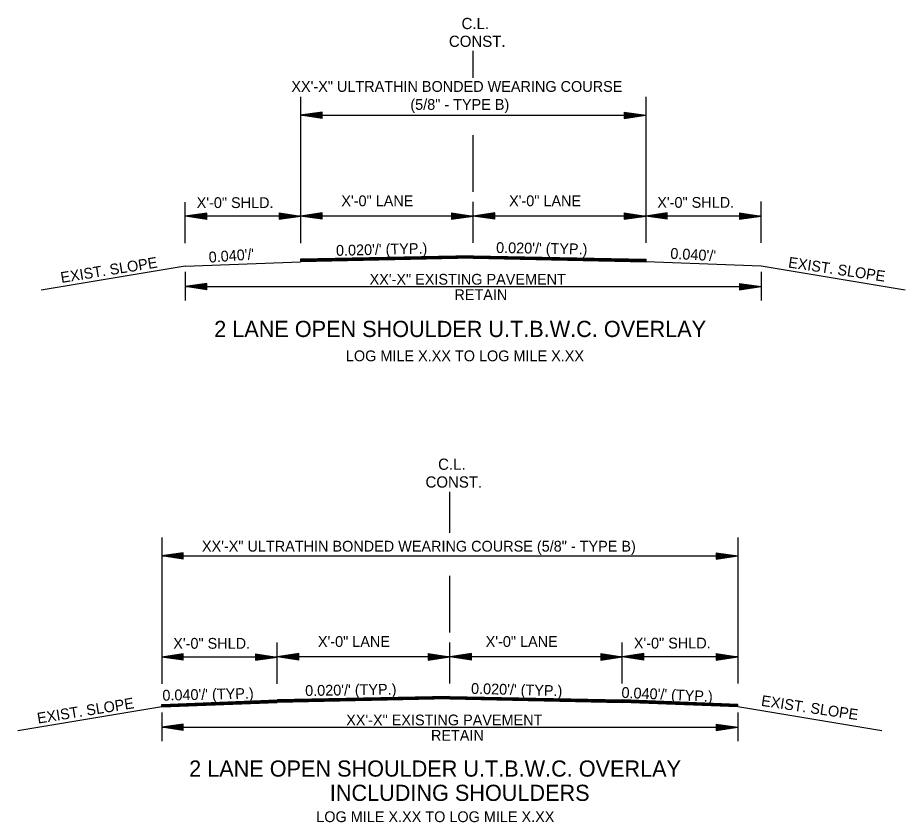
# Model space of a CAD drawing. Extents: x 544199 to 1930787, y -1968972 to 596640.
# Drawn here: x 551654 to 552271, y -1951988 to -1951428 of the extents above; entities that cross this region are included whole.
import ezdxf

# ---------------------------------------------------------------- set-up
doc = ezdxf.new("R2010")
doc.units = 0
doc.layers.add('Default', color=7, linetype='Continuous')
doc.layers.add('R_Draft', color=7, linetype='Continuous')

msp = doc.modelspace()

# ---------------------------------------------------------------- linework, layer by layer
at = {"layer": 'R_Draft'}
for p, q in [((551970.96, -1951470.01), (551970.96, -1951451.34)), ((551850.96, -1951483.29), (551850.96, -1951585.02)), ((551865.96, -1951493.8), (551850.96, -1951496.05)), ((551850.96, -1951496.05), (552090.89, -1951496.05)), ((551865.96, -1951498.3), (551850.96, -1951496.05)), ((551865.96, -1951494.18), (551853.46, -1951496.05)), ((551865.96, -1951497.93), (551853.46, -1951496.05)), ((551865.96, -1951494.56), (551856.04, -1951496.05)), ((551865.96, -1951497.54), (551856.04, -1951496.05)), ((551865.96, -1951494.93), (551858.54, -1951496.05)), ((551865.96, -1951497.17), (551858.54, -1951496.05)), ((551865.96, -1951495.32), (551861.08, -1951496.05)), ((551865.96, -1951496.78), (551861.08, -1951496.05)), ((551865.96, -1951495.7), (551863.59, -1951496.05)), ((551865.96, -1951496.4), (551863.59, -1951496.05)), ((551865.96, -1951498.3), (551865.96, -1951493.8)), ((552075.89, -1951493.8), (552090.89, -1951496.05)), ((552075.89, -1951493.8), (552075.89, -1951498.3)), ((552075.89, -1951494.18), (552088.38, -1951496.05)), ((552075.89, -1951494.56), (552085.8, -1951496.05)), ((552075.89, -1951494.93), (552083.3, -1951496.05)), ((552075.89, -1951495.32), (552080.76, -1951496.05)), ((552075.89, -1951495.7), (552078.26, -1951496.05)), ((552075.89, -1951498.3), (552090.89, -1951496.05)), ((552075.89, -1951496.79), (552080.76, -1951496.05)), ((552075.89, -1951497.54), (552085.8, -1951496.05)), ((552075.89, -1951497.93), (552088.38, -1951496.05)), ((552075.89, -1951497.17), (552083.3, -1951496.05)), ((552075.89, -1951496.4), (552078.26, -1951496.05)), ((551970.96, -1951549.29), (551970.96, -1951509.94)), ((551770.7, -1951585.02), (551770.7, -1951556.47)), ((551970.96, -1951584.85), (551970.96, -1951556.3)), ((552171.15, -1951584.85), (552171.15, -1951556.13)), ((551785.7, -1951564.11), (551770.7, -1951566.36)), ((551850.96, -1951566.36), (551770.7, -1951566.36)), ((551785.7, -1951568.61), (551770.7, -1951566.36)), ((551785.7, -1951564.49), (551773.2, -1951566.36)), ((551785.7, -1951568.24), (551773.2, -1951566.36)), ((551785.7, -1951564.87), (551775.78, -1951566.36)), ((551785.7, -1951567.86), (551775.78, -1951566.36)), ((551785.7, -1951565.25), (551778.28, -1951566.36)), ((551785.7, -1951567.48), (551778.28, -1951566.36)), ((551785.7, -1951565.63), (551780.82, -1951566.36)), ((551785.7, -1951567.09), (551780.82, -1951566.36)), ((551785.7, -1951566.01), (551783.33, -1951566.36)), ((551785.7, -1951566.72), (551783.33, -1951566.36)), ((551785.7, -1951568.61), (551785.7, -1951564.11)), ((551835.96, -1951563.94), (551850.96, -1951566.19)), ((551835.96, -1951563.94), (551835.96, -1951568.44)), ((551835.96, -1951564.32), (551848.45, -1951566.19)), ((551835.96, -1951564.7), (551845.87, -1951566.19)), ((551835.96, -1951565.08), (551843.38, -1951566.19)), ((551835.96, -1951565.47), (551840.83, -1951566.19)), ((551835.96, -1951565.84), (551838.33, -1951566.19)), ((551835.96, -1951568.44), (551850.96, -1951566.19)), ((551835.96, -1951566.93), (551840.83, -1951566.19)), ((551835.96, -1951567.69), (551845.87, -1951566.19)), ((551835.96, -1951568.07), (551848.45, -1951566.19)), ((551835.96, -1951567.31), (551843.38, -1951566.19)), ((551835.96, -1951566.55), (551838.33, -1951566.19)), ((551865.96, -1951563.94), (551850.96, -1951566.19)), ((551970.96, -1951566.19), (551850.96, -1951566.19)), ((551865.96, -1951568.44), (551850.96, -1951566.19)), ((551865.96, -1951564.32), (551853.46, -1951566.19)), ((551865.96, -1951568.07), (551853.46, -1951566.19)), ((551865.96, -1951564.7), (551856.04, -1951566.19)), ((551865.96, -1951567.69), (551856.04, -1951566.19)), ((551865.96, -1951565.08), (551858.54, -1951566.19)), ((551865.96, -1951567.31), (551858.54, -1951566.19)), ((551865.96, -1951565.46), (551861.08, -1951566.19)), ((551865.96, -1951566.92), (551861.08, -1951566.19)), ((551865.96, -1951565.84), (551863.59, -1951566.19)), ((551865.96, -1951566.55), (551863.59, -1951566.19)), ((551865.96, -1951568.44), (551865.96, -1951563.94)), ((551955.96, -1951563.94), (551970.96, -1951566.19)), ((551955.96, -1951563.94), (551955.96, -1951568.44)), ((551955.96, -1951564.32), (551968.45, -1951566.19)), ((551955.96, -1951564.7), (551965.87, -1951566.19)), ((551955.96, -1951565.08), (551963.38, -1951566.19)), ((551955.96, -1951565.47), (551960.83, -1951566.19)), ((551955.96, -1951565.84), (551958.33, -1951566.19)), ((551955.96, -1951568.44), (551970.96, -1951566.19)), ((551955.96, -1951566.93), (551960.83, -1951566.19)), ((551955.96, -1951567.69), (551965.87, -1951566.19)), ((551955.96, -1951568.07), (551968.45, -1951566.19)), ((551955.96, -1951567.31), (551963.38, -1951566.19)), ((551955.96, -1951566.55), (551958.33, -1951566.19)), ((551985.96, -1951563.94), (551970.96, -1951566.19)), ((552090.89, -1951566.19), (551970.96, -1951566.19)), ((551985.96, -1951568.44), (551970.96, -1951566.19)), ((551985.96, -1951564.32), (551973.46, -1951566.19)), ((551985.96, -1951568.07), (551973.46, -1951566.19)), ((551985.96, -1951564.7), (551976.04, -1951566.19)), ((551985.96, -1951567.69), (551976.04, -1951566.19)), ((551985.96, -1951565.08), (551978.54, -1951566.19)), ((551985.96, -1951567.31), (551978.54, -1951566.19)), ((551985.96, -1951565.46), (551981.08, -1951566.19)), ((551985.96, -1951566.92), (551981.08, -1951566.19)), ((551985.96, -1951565.84), (551983.59, -1951566.19)), ((551985.96, -1951566.55), (551983.59, -1951566.19)), ((551985.96, -1951568.44), (551985.96, -1951563.94)), ((552075.89, -1951563.94), (552090.89, -1951566.19)), ((552075.89, -1951563.94), (552075.89, -1951568.44)), ((552075.89, -1951564.32), (552088.38, -1951566.19)), ((552075.89, -1951564.7), (552085.8, -1951566.19)), ((552075.89, -1951565.08), (552083.3, -1951566.19)), ((552075.89, -1951565.47), (552080.76, -1951566.19)), ((552075.89, -1951565.84), (552078.26, -1951566.19)), ((552075.89, -1951568.44), (552090.89, -1951566.19)), ((552075.89, -1951566.93), (552080.76, -1951566.19)), ((552075.89, -1951567.69), (552085.8, -1951566.19)), ((552075.89, -1951568.07), (552088.38, -1951566.19)), ((552075.89, -1951567.31), (552083.3, -1951566.19)), ((552075.89, -1951566.55), (552078.26, -1951566.19)), ((552105.89, -1951563.94), (552090.89, -1951566.19)), ((552171.15, -1951566.19), (552090.89, -1951566.19)), ((552105.89, -1951568.44), (552090.89, -1951566.19)), ((552105.89, -1951564.32), (552093.39, -1951566.19)), ((552105.89, -1951568.07), (552093.39, -1951566.19)), ((552105.89, -1951564.7), (552095.97, -1951566.19)), ((552105.89, -1951567.69), (552095.97, -1951566.19)), ((552105.89, -1951565.08), (552098.47, -1951566.19)), ((552105.89, -1951567.31), (552098.47, -1951566.19)), ((552105.89, -1951565.46), (552101.01, -1951566.19)), ((552105.89, -1951566.92), (552101.01, -1951566.19)), ((552105.89, -1951565.84), (552103.52, -1951566.19)), ((552105.89, -1951566.55), (552103.52, -1951566.19)), ((552105.89, -1951568.44), (552105.89, -1951563.94)), ((552156.15, -1951563.94), (552171.15, -1951566.19)), ((552156.15, -1951563.94), (552156.15, -1951568.44)), ((552156.15, -1951564.32), (552168.64, -1951566.19)), ((552156.15, -1951564.7), (552166.06, -1951566.19)), ((552156.15, -1951565.08), (552163.56, -1951566.19)), ((552156.15, -1951565.47), (552161.02, -1951566.19)), ((552156.15, -1951565.84), (552158.52, -1951566.19)), ((552156.15, -1951568.44), (552171.15, -1951566.19)), ((552156.15, -1951566.93), (552161.02, -1951566.19)), ((552156.15, -1951567.69), (552166.06, -1951566.19)), ((552156.15, -1951568.07), (552168.64, -1951566.19)), ((552156.15, -1951567.31), (552163.56, -1951566.19)), ((552156.15, -1951566.55), (552158.52, -1951566.19)), ((551970.96, -1951593.8), (551850.96, -1951596.2)), ((551850.96, -1951596.2), (551850.99, -1951597.9)), ((551970.97, -1951594.1), (551850.97, -1951596.5)), ((551970.97, -1951594.4), (551850.97, -1951596.8)), ((551970.98, -1951594.7), (551850.98, -1951597.1)), ((551970.98, -1951595), (551850.98, -1951597.4)), ((551970.99, -1951595.3), (551850.99, -1951597.7)), ((551970.99, -1951595.5), (551850.99, -1951597.9)), ((551970.93, -1951595.3), (552090.93, -1951597.7)), ((551970.93, -1951595.5), (552090.93, -1951597.9)), ((551970.94, -1951594.7), (552090.94, -1951597.1)), ((551970.94, -1951595), (552090.94, -1951597.4)), ((551970.95, -1951594.1), (552090.95, -1951596.5)), ((551970.95, -1951594.4), (552090.95, -1951596.8)), ((551970.96, -1951593.8), (552090.96, -1951596.2)), ((552090.96, -1951596.2), (552090.93, -1951597.9)), ((551770.7, -1951601.11), (551670.63, -1951617.79)), ((551770.7, -1951601.11), (551850.99, -1951597.9)), ((552171.22, -1951601.11), (552090.93, -1951597.9)), ((552271.29, -1951617.79), (552171.22, -1951601.11)), ((551770.7, -1951604.97), (551770.7, -1951624.97)), ((552171.15, -1951604.97), (552171.15, -1951624.97)), ((551785.7, -1951612.97), (551770.7, -1951615.22)), ((551770.7, -1951615.22), (552171.15, -1951615.22)), ((551785.7, -1951617.47), (551770.7, -1951615.22)), ((551785.7, -1951613.34), (551773.2, -1951615.22)), ((551785.7, -1951617.09), (551773.2, -1951615.22)), ((551785.7, -1951613.72), (551775.78, -1951615.22)), ((551785.7, -1951616.71), (551775.78, -1951615.22)), ((551785.7, -1951614.1), (551778.28, -1951615.22)), ((551785.7, -1951616.33), (551778.28, -1951615.22)), ((551785.7, -1951614.48), (551780.82, -1951615.22)), ((551785.7, -1951615.94), (551780.82, -1951615.22)), ((551785.7, -1951614.86), (551783.33, -1951615.22)), ((551785.7, -1951615.57), (551783.33, -1951615.22)), ((551785.7, -1951617.47), (551785.7, -1951612.97)), ((552156.15, -1951612.97), (552171.15, -1951615.22)), ((552156.15, -1951612.97), (552156.15, -1951617.47)), ((552156.15, -1951613.34), (552168.64, -1951615.22)), ((552156.15, -1951613.72), (552166.06, -1951615.22)), ((552156.15, -1951614.1), (552163.56, -1951615.22)), ((552156.15, -1951614.49), (552161.02, -1951615.22)), ((552156.15, -1951614.86), (552158.52, -1951615.22)), ((552156.15, -1951617.47), (552171.15, -1951615.22)), ((552156.15, -1951615.95), (552161.02, -1951615.22)), ((552156.15, -1951616.71), (552166.06, -1951615.22)), ((552156.15, -1951617.09), (552168.64, -1951615.22)), ((552156.15, -1951616.33), (552163.56, -1951615.22)), ((552156.15, -1951615.57), (552158.52, -1951615.22)), ((551954.68, -1951786.52), (551954.68, -1951757.88)), ((551754.42, -1951789.83), (551754.42, -1951891.56)), ((551769.42, -1951800.34), (551754.42, -1951802.59)), ((551769.42, -1951800.72), (551756.93, -1951802.59)), ((551769.42, -1951801.1), (551759.51, -1951802.59)), ((551769.42, -1951804.84), (551769.42, -1951800.34)), ((552139.87, -1951800.34), (552154.87, -1951802.59)), ((552139.87, -1951800.34), (552139.87, -1951804.84)), ((552139.87, -1951800.72), (552152.36, -1951802.59)), ((552139.87, -1951801.1), (552149.78, -1951802.59)), ((551754.42, -1951802.59), (552154.87, -1951802.59)), ((551769.42, -1951804.84), (551754.42, -1951802.59)), ((551769.42, -1951804.47), (551756.93, -1951802.59)), ((551769.42, -1951804.08), (551759.51, -1951802.59)), ((551769.42, -1951801.47), (551762, -1951802.59)), ((551769.42, -1951803.71), (551762, -1951802.59)), ((551769.42, -1951801.86), (551764.55, -1951802.59)), ((551769.42, -1951803.32), (551764.55, -1951802.59)), ((551769.42, -1951802.24), (551767.05, -1951802.59)), ((551769.42, -1951802.94), (551767.05, -1951802.59)), ((552139.87, -1951801.47), (552147.29, -1951802.59)), ((552139.87, -1951801.86), (552144.74, -1951802.59)), ((552139.87, -1951802.24), (552142.24, -1951802.59)), ((552139.87, -1951804.84), (552154.87, -1951802.59)), ((552139.87, -1951803.33), (552144.74, -1951802.59)), ((552139.87, -1951804.08), (552149.78, -1951802.59)), ((552139.87, -1951804.47), (552152.36, -1951802.59)), ((552139.87, -1951803.71), (552147.29, -1951802.59)), ((552139.87, -1951802.94), (552142.24, -1951802.59)), ((551954.68, -1951855.83), (551954.68, -1951816.48)), ((551834.68, -1951891.39), (551834.68, -1951862.84)), ((551834.68, -1951891.56), (551834.68, -1951862.84)), ((551954.68, -1951891.39), (551954.68, -1951862.84)), ((552074.61, -1951872.73), (552074.61, -1951862.84)), ((552074.61, -1951891.39), (552074.61, -1951862.84)), ((551769.42, -1951870.65), (551754.42, -1951872.9)), ((551834.68, -1951872.9), (551754.42, -1951872.9)), ((551769.42, -1951875.15), (551754.42, -1951872.9)), ((551769.42, -1951871.03), (551756.93, -1951872.9)), ((551769.42, -1951874.78), (551756.93, -1951872.9)), ((551769.42, -1951871.41), (551759.51, -1951872.9)), ((551769.42, -1951874.4), (551759.51, -1951872.9)), ((551769.42, -1951871.79), (551762, -1951872.9)), ((551769.42, -1951874.02), (551762, -1951872.9)), ((551769.42, -1951872.17), (551764.55, -1951872.9)), ((551769.42, -1951873.63), (551764.55, -1951872.9)), ((551769.42, -1951872.55), (551767.05, -1951872.9)), ((551769.42, -1951873.26), (551767.05, -1951872.9)), ((551769.42, -1951875.15), (551769.42, -1951870.65)), ((551819.68, -1951870.65), (551834.68, -1951872.9)), ((551819.68, -1951870.65), (551819.68, -1951875.15)), ((551819.68, -1951871.03), (551832.18, -1951872.9)), ((551819.68, -1951871.41), (551829.6, -1951872.9)), ((551819.68, -1951871.79), (551827.1, -1951872.9)), ((551819.68, -1951872.18), (551824.56, -1951872.9)), ((551819.68, -1951872.55), (551822.05, -1951872.9)), ((551819.68, -1951875.15), (551834.68, -1951872.9)), ((551819.68, -1951873.64), (551824.56, -1951872.9)), ((551819.68, -1951874.4), (551829.6, -1951872.9)), ((551819.68, -1951874.78), (551832.18, -1951872.9)), ((551819.68, -1951874.02), (551827.1, -1951872.9)), ((551819.68, -1951873.26), (551822.05, -1951872.9)), ((551849.68, -1951870.48), (551834.68, -1951872.73)), ((551954.68, -1951872.73), (551834.68, -1951872.73)), ((551849.68, -1951874.98), (551834.68, -1951872.73)), ((551849.68, -1951870.86), (551837.19, -1951872.73)), ((551849.68, -1951874.61), (551837.19, -1951872.73)), ((551849.68, -1951871.24), (551839.77, -1951872.73)), ((551849.68, -1951874.23), (551839.77, -1951872.73)), ((551849.68, -1951871.62), (551842.26, -1951872.73)), ((551849.68, -1951873.85), (551842.26, -1951872.73)), ((551849.68, -1951872), (551844.81, -1951872.73)), ((551849.68, -1951873.46), (551844.81, -1951872.73)), ((551849.68, -1951872.38), (551847.31, -1951872.73)), ((551849.68, -1951873.09), (551847.31, -1951872.73)), ((551849.68, -1951874.98), (551849.68, -1951870.48)), ((551939.68, -1951870.48), (551954.68, -1951872.73)), ((551939.68, -1951870.48), (551939.68, -1951874.98)), ((551939.68, -1951870.86), (551952.18, -1951872.73)), ((551939.68, -1951871.24), (551949.6, -1951872.73)), ((551939.68, -1951871.62), (551947.1, -1951872.73)), ((551939.68, -1951872.01), (551944.56, -1951872.73)), ((551939.68, -1951872.38), (551942.05, -1951872.73)), ((551939.68, -1951874.98), (551954.68, -1951872.73)), ((551939.68, -1951873.47), (551944.56, -1951872.73)), ((551939.68, -1951874.23), (551949.6, -1951872.73)), ((551939.68, -1951874.61), (551952.18, -1951872.73)), ((551939.68, -1951873.85), (551947.1, -1951872.73)), ((551939.68, -1951873.09), (551942.05, -1951872.73)), ((551969.68, -1951870.48), (551954.68, -1951872.73)), ((552074.61, -1951872.73), (551954.68, -1951872.73)), ((551969.68, -1951874.98), (551954.68, -1951872.73)), ((551969.68, -1951870.86), (551957.19, -1951872.73)), ((551969.68, -1951874.61), (551957.19, -1951872.73)), ((551969.68, -1951871.24), (551959.77, -1951872.73)), ((551969.68, -1951874.23), (551959.77, -1951872.73)), ((551969.68, -1951871.62), (551962.26, -1951872.73)), ((551969.68, -1951873.85), (551962.26, -1951872.73)), ((551969.68, -1951872), (551964.81, -1951872.73)), ((551969.68, -1951873.46), (551964.81, -1951872.73)), ((551969.68, -1951872.38), (551967.31, -1951872.73)), ((551969.68, -1951873.09), (551967.31, -1951872.73)), ((551969.68, -1951874.98), (551969.68, -1951870.48)), ((552059.61, -1951870.48), (552074.61, -1951872.73)), ((552059.61, -1951870.48), (552059.61, -1951874.98)), ((552059.61, -1951870.86), (552072.1, -1951872.73)), ((552059.61, -1951871.24), (552069.52, -1951872.73)), ((552059.61, -1951871.62), (552067.03, -1951872.73)), ((552059.61, -1951872.01), (552064.48, -1951872.73)), ((552059.61, -1951872.38), (552061.98, -1951872.73)), ((552059.61, -1951874.98), (552074.61, -1951872.73)), ((552059.61, -1951873.47), (552064.48, -1951872.73)), ((552059.61, -1951874.23), (552069.52, -1951872.73)), ((552059.61, -1951874.61), (552072.1, -1951872.73)), ((552059.61, -1951873.85), (552067.03, -1951872.73)), ((552059.61, -1951873.09), (552061.98, -1951872.73)), ((552089.61, -1951870.48), (552074.61, -1951872.73)), ((552074.61, -1951891.39), (552074.61, -1951872.73)), ((552154.87, -1951872.73), (552074.61, -1951872.73)), ((552089.61, -1951874.98), (552074.61, -1951872.73)), ((552089.61, -1951870.86), (552077.11, -1951872.73)), ((552089.61, -1951874.61), (552077.11, -1951872.73)), ((552089.61, -1951871.24), (552079.69, -1951872.73)), ((552089.61, -1951874.23), (552079.69, -1951872.73)), ((552089.61, -1951871.62), (552082.19, -1951872.73)), ((552089.61, -1951873.85), (552082.19, -1951872.73)), ((552089.61, -1951872), (552084.73, -1951872.73)), ((552089.61, -1951873.46), (552084.73, -1951872.73)), ((552089.61, -1951872.38), (552087.24, -1951872.73)), ((552089.61, -1951873.09), (552087.24, -1951872.73)), ((552089.61, -1951874.98), (552089.61, -1951870.48)), ((552139.87, -1951870.48), (552154.87, -1951872.73)), ((552139.87, -1951870.48), (552139.87, -1951874.98)), ((552139.87, -1951870.86), (552152.36, -1951872.73)), ((552139.87, -1951871.24), (552149.78, -1951872.73)), ((552139.87, -1951871.62), (552147.29, -1951872.73)), ((552139.87, -1951872.01), (552144.74, -1951872.73)), ((552139.87, -1951872.38), (552142.24, -1951872.73)), ((552139.87, -1951874.98), (552154.87, -1951872.73)), ((552139.87, -1951873.47), (552144.74, -1951872.73)), ((552139.87, -1951874.23), (552149.78, -1951872.73)), ((552139.87, -1951874.61), (552152.36, -1951872.73)), ((552139.87, -1951873.85), (552147.29, -1951872.73)), ((552139.87, -1951873.09), (552142.24, -1951872.73)), ((551754.42, -1951905.95), (551834.68, -1951902.74)), ((551754.42, -1951906.25), (551834.69, -1951903.04)), ((551754.42, -1951906.55), (551834.71, -1951903.34)), ((551754.42, -1951906.85), (551834.72, -1951903.64)), ((551754.42, -1951907.15), (551834.73, -1951903.94)), ((551754.42, -1951907.45), (551834.74, -1951904.24)), ((551754.42, -1951907.65), (551834.75, -1951904.44)), ((551754.42, -1951907.65), (551754.42, -1951905.95)), ((551954.68, -1951900.34), (551834.68, -1951902.74)), ((551954.69, -1951900.64), (551834.69, -1951903.04)), ((551954.69, -1951900.94), (551834.69, -1951903.34)), ((551954.7, -1951901.24), (551834.7, -1951903.64)), ((551954.71, -1951901.54), (551834.71, -1951903.94)), ((551954.71, -1951901.84), (551834.71, -1951904.24)), ((551954.72, -1951902.04), (551834.72, -1951904.44)), ((551954.65, -1951901.84), (552074.65, -1951904.24)), ((551954.65, -1951902.04), (552074.65, -1951904.44)), ((551954.66, -1951901.24), (552074.66, -1951903.64)), ((551954.66, -1951901.54), (552074.66, -1951903.94)), ((551954.67, -1951900.94), (552074.67, -1951903.34)), ((551954.68, -1951900.34), (552074.68, -1951902.74)), ((551954.68, -1951900.64), (552074.68, -1951903.04)), ((552154.94, -1951907.65), (552074.61, -1951904.44)), ((552154.94, -1951907.45), (552074.62, -1951904.24)), ((552154.94, -1951907.15), (552074.63, -1951903.94)), ((552154.94, -1951906.85), (552074.65, -1951903.64)), ((552154.94, -1951906.55), (552074.66, -1951903.34)), ((552154.94, -1951906.25), (552074.67, -1951903.04)), ((552154.94, -1951905.95), (552074.68, -1951902.74)), ((552154.94, -1951907.65), (552154.94, -1951905.95)), ((551754.42, -1951907.65), (551654.35, -1951924.33)), ((551754.42, -1951911.51), (551754.42, -1951931.51)), ((552154.87, -1951911.51), (552154.87, -1951931.51)), ((552255.01, -1951924.33), (552154.94, -1951907.65)), ((551769.42, -1951919.5), (551754.42, -1951921.75)), ((551754.42, -1951921.75), (552154.87, -1951921.75)), ((551769.42, -1951924), (551754.42, -1951921.75)), ((551769.42, -1951919.88), (551756.93, -1951921.75)), ((551769.42, -1951923.63), (551756.93, -1951921.75)), ((551769.42, -1951920.26), (551759.51, -1951921.75)), ((551769.42, -1951923.25), (551759.51, -1951921.75)), ((551769.42, -1951920.64), (551762, -1951921.75)), ((551769.42, -1951922.87), (551762, -1951921.75)), ((551769.42, -1951921.02), (551764.55, -1951921.75)), ((551769.42, -1951922.48), (551764.55, -1951921.75)), ((551769.42, -1951921.4), (551767.05, -1951921.75)), ((551769.42, -1951922.11), (551767.05, -1951921.75)), ((551769.42, -1951924), (551769.42, -1951919.5)), ((552139.87, -1951919.5), (552154.87, -1951921.75)), ((552139.87, -1951919.5), (552139.87, -1951924)), ((552139.87, -1951919.88), (552152.36, -1951921.75)), ((552139.87, -1951920.26), (552149.78, -1951921.75)), ((552139.87, -1951920.64), (552147.29, -1951921.75)), ((552139.87, -1951921.03), (552144.74, -1951921.75)), ((552139.87, -1951921.4), (552142.24, -1951921.75)), ((552139.87, -1951924), (552154.87, -1951921.75)), ((552139.87, -1951922.49), (552144.74, -1951921.75)), ((552139.87, -1951923.25), (552149.78, -1951921.75)), ((552139.87, -1951923.63), (552152.36, -1951921.75)), ((552139.87, -1951922.87), (552147.29, -1951921.75)), ((552139.87, -1951922.11), (552142.24, -1951921.75))]:
    msp.add_line(p, q, dxfattribs=at)
for points in [[(552090.89, -1951483.29), (552090.89, -1951584.85)], [(552154.87, -1951789.83), (552154.87, -1951891.39)]]:
    msp.add_lwpolyline(points, dxfattribs=at)

# ---------------------------------------------------------------- texts
at = {"layer": 'Default'}
for s, p in [('XX\'-X" EXISTING PAVEMENT', (551898.94, -1951613.89)), ('RETAIN', (551957.88, -1951624.62)), ('XX\'-X" EXISTING PAVEMENT', (551882.66, -1951920.43)), ('RETAIN', (551941.6, -1951931.15))]:
    msp.add_text(s, height=7.5, dxfattribs=at).set_placement(p)
at = {"layer": 'R_Draft'}
for s, height, p in [('C.L.', 7.8, (551962.86, -1951436.14)), ('CONST.', 7.8, (551954.07, -1951448.51)), ('XX\'-X" ULTRATHIN BONDED WEARING COURSE', 7.5, (551844.57, -1951479.78)), ('(5/8" - TYPE B)', 7.5, (551927.27, -1951492.29)), ('X\'-0" SHLD.', 7.5, (551778.73, -1951560.59)), ('X\'-0" LANE', 7.5, (551879.3, -1951559.33)), ('X\'-0" LANE', 7.5, (551995.89, -1951559.33)), ('X\'-0" SHLD.', 7.5, (552098.92, -1951560.42)), ('2 LANE OPEN SHOULDER U.T.B.W.C. OVERLAY', 11.25, (551790.92, -1951650.3)), ('LOG MILE X.XX TO LOG MILE X.XX', 7.5, (551882.46, -1951667.16)), ('C.L.', 7.8, (551946.58, -1951742.68)), ('CONST.', 7.8, (551937.8, -1951755.05)), ('XX\'-X" ULTRATHIN BONDED WEARING COURSE (5/8" - TYPE B)', 7.5, (551782.4, -1951799.57)), ('X\'-0" SHLD.', 7.5, (551762.46, -1951867.13)), ('X\'-0" LANE', 7.5, (551863.02, -1951865.87)), ('X\'-0" LANE', 7.5, (551979.62, -1951865.87)), ('X\'-0" SHLD.', 7.5, (552082.64, -1951866.96)), ('2 LANE OPEN SHOULDER U.T.B.W.C. OVERLAY', 11.25, (551773.5, -1951956.09)), ('INCLUDING SHOULDERS', 11.25, (551871.29, -1951972.97)), ('LOG MILE X.XX TO LOG MILE X.XX', 7.5, (551861.88, -1951987.73))]:
    msp.add_text(s, height=height, dxfattribs=at).set_placement(p)
for s, rotation, p in [("0.020'/' (TYP.)", 1.42536, (551875.67, -1951593.85)), ("0.020'/' (TYP.)", 359.06285, (551986.83, -1951591.84)), ("0.040'/'", 4.25245, (551787.36, -1951598.6)), ("0.040'/'", 356.79663, (552107.81, -1951595.8)), ('EXIST. SLOPE', 9.15344, (551684.74, -1951612.73)), ('EXIST. SLOPE', 351.57554, (552189.59, -1951601.9)), ("0.020'/' (TYP.)", 0.97192, (551854.2, -1951900.03)), ("0.020'/' (TYP.)", 358.5057, (551969.38, -1951898.5)), ("0.040'/' (TYP.)", 357.39273, (552073.9, -1951901.22)), ("0.040'/' (TYP.)", 1.31838, (551754.98, -1951903.28)), ('EXIST. SLOPE', 351.57554, (552170.77, -1951906.82)), ('EXIST. SLOPE', 9.15344, (551668.46, -1951919.26))]:
    msp.add_text(s, height=7.5, rotation=rotation, dxfattribs=at).set_placement(p)

doc.saveas('drawing.dxf')
